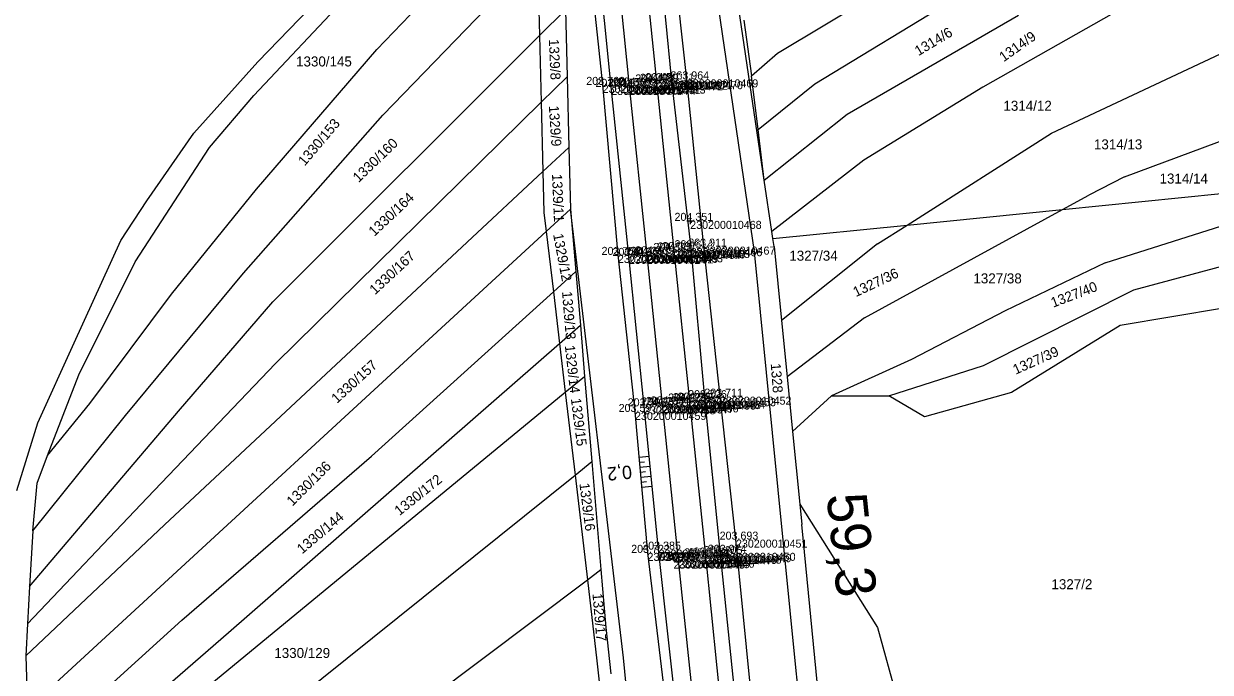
# Model space of a CAD drawing. Extents: x -563148 to -561712, y -1182311 to -1179502.
# Drawn here: x -562607.2 to -562429.3, y -1181480.3 to -1181383.1 of the extents above; entities that cross this region are included whole.
import ezdxf

# ---------------------------------------------------------------- set-up
doc = ezdxf.new("R2010")
doc.units = 0
for name, color, linetype in [('Vrstva 1', 7, 'Continuous'), ('Vrstva 4', 7, 'Continuous'), ('Vrstva 48', 7, 'Continuous'), ('Vrstva 49', 7, 'Continuous'), ('Vrstva 53', 7, 'Continuous'), ('Vrstva 55', 7, 'Continuous'), ('Vrstva 57', 7, 'Continuous'), ('Vrstva 60', 7, 'Continuous'), ('Vrstva 61', 7, 'Continuous'), ('Vrstva 7', 7, 'Continuous')]:
    doc.layers.add(name, color=color, linetype=linetype)

msp = doc.modelspace()

# ---------------------------------------------------------------- linework, layer by layer
at = {"layer": 'Vrstva 1'}
for points in [[(-562538.22, -1181140.47), (-562535.7, -1181165), (-562533.31, -1181188.28), (-562530.86, -1181211.96), (-562528.58, -1181233.98), (-562526.26, -1181256.44), (-562523.94, -1181279), (-562521.9, -1181298.94), (-562519.98, -1181317.53), (-562517.8, -1181338.73), (-562515.33, -1181362.72), (-562512.33, -1181391.8), (-562509.71, -1181417.08), (-562507.39, -1181439.64), (-562504.99, -1181462.85), (-562502.4, -1181488), (-562497.18, -1181538.47), (-562494.78, -1181561.72), (-562492, -1181588.79)], [(-562542.31, -1181141.05), (-562539.78, -1181165.62), (-562537.38, -1181188.86), (-562535, -1181212.18), (-562532.67, -1181234.54), (-562530.35, -1181257.17), (-562528.02, -1181279.67), (-562526.02, -1181298.95), (-562524.04, -1181318.17), (-562521.85, -1181339.36), (-562519.38, -1181363.29), (-562516.39, -1181392.45), (-562513.77, -1181417.73), (-562511.45, -1181440.22), (-562509.05, -1181463.48), (-562506.44, -1181488.7), (-562501.23, -1181539.12), (-562498.83, -1181562.33), (-562496.03, -1181589.56)]]:
    msp.add_lwpolyline(points, dxfattribs=at)
at = {"layer": 'Vrstva 4'}
for points in [[(-562530.95, -1181181.8), (-562531.11, -1181188.17), (-562528.51, -1181211.79), (-562526.22, -1181233.69), (-562523.84, -1181256.06), (-562521.66, -1181278.67), (-562519.62, -1181298.82), (-562517.74, -1181317.29), (-562515.5, -1181338.48), (-562512.91, -1181362.61), (-562510.06, -1181391.72), (-562507.16, -1181416.74), (-562505.12, -1181439.21), (-562502.78, -1181462.58), (-562500.17, -1181487.79), (-562494.92, -1181538.43), (-562492.69, -1181561.57), (-562489.58, -1181589.45)], [(-562492.85, -1181639.28), (-562495.8, -1181615.87), (-562498.53, -1181589.76), (-562501.43, -1181562.22), (-562503.74, -1181539.41), (-562508.99, -1181488.94), (-562512, -1181461.9), (-562514.18, -1181440.43), (-562516.46, -1181417.89), (-562519.11, -1181392.57), (-562522.07, -1181363.22), (-562524.36, -1181339.65), (-562526.91, -1181316.04), (-562528.67, -1181299.17), (-562530.86, -1181280.31), (-562533.06, -1181257.38), (-562535.11, -1181235.07), (-562537.81, -1181212.62), (-562539.6, -1181193.44), (-562540.41, -1181189.21)]]:
    msp.add_lwpolyline(points, dxfattribs=at)
at = {"layer": 'Vrstva 48'}
for p, q in [((-562514.93, -1181448.04), (-562513.42, -1181447.9)), ((-562514.87, -1181448.79), (-562514.11, -1181448.72)), ((-562514.8, -1181449.53), (-562513.27, -1181449.4)), ((-562514.73, -1181450.28), (-562513.96, -1181450.21)), ((-562514.67, -1181451.03), (-562513.12, -1181450.89)), ((-562514.6, -1181451.77), (-562513.82, -1181451.7)), ((-562514.54, -1181452.52), (-562512.97, -1181452.38))]:
    msp.add_line(p, q, dxfattribs=at)
at = {"layer": 'Vrstva 49'}
for points in [[(-562512.91, -1181362.61), (-562510.06, -1181391.72), (-562507.16, -1181416.74), (-562505.12, -1181439.21), (-562502.79, -1181438.98)], [(-562502.79, -1181438.98), (-562505.2, -1181416.5), (-562507.77, -1181391.44), (-562510.96, -1181362.42)], [(-562494.74, -1181639.25), (-562492.85, -1181639.28), (-562495.8, -1181615.87), (-562498.53, -1181589.76), (-562501.43, -1181562.22), (-562503.74, -1181539.41), (-562508.99, -1181488.94), (-562512, -1181461.9), (-562514.18, -1181440.43), (-562516.46, -1181417.89), (-562519.11, -1181392.57), (-562522.07, -1181363.22), (-562523.47, -1181363.71)], [(-562523.47, -1181363.71), (-562520.39, -1181392.27), (-562518.1, -1181417.74), (-562515.54, -1181441.27), (-562513.66, -1181462.38), (-562510.65, -1181487.32), (-562505.3, -1181539.56), (-562502.96, -1181562.74), (-562500.08, -1181589.68), (-562497.19, -1181615.94), (-562494.74, -1181639.25)], [(-562505.12, -1181439.21), (-562502.78, -1181462.58), (-562500.17, -1181487.79), (-562494.92, -1181538.43), (-562492.69, -1181561.57), (-562489.58, -1181589.45)], [(-562487.28, -1181589.39), (-562490.19, -1181561.46), (-562492.66, -1181538.42), (-562497.73, -1181487.61), (-562500.4, -1181460.4), (-562502.79, -1181438.98)]]:
    msp.add_lwpolyline(points, dxfattribs=at)
at = {"layer": 'Vrstva 53'}
for p, q in [((-562508.1, -1181346.18), (-562497.67, -1181417.28)), ((-562525.96, -1181381), (-562525.71, -1181391.05)), ((-562525.71, -1181391.05), (-562525.44, -1181401.63)), ((-562525.44, -1181401.63), (-562525.2, -1181410.9)), ((-562517.26, -1181478.11), (-562525.2, -1181410.9)), ((-562497.67, -1181417.28), (-562491.4, -1181480.04)), ((-562490.83, -1181455.09), (-562490.53, -1181458.12)), ((-562490.83, -1181455.09), (-562479.17, -1181473.55)), ((-562485.92, -1181504.93), (-562490.53, -1181458.12)), ((-562479.17, -1181473.55), (-562475.52, -1181486.71)), ((-562512.39, -1181525.85), (-562517.26, -1181478.11)), ((-562491.4, -1181480.04), (-562486.34, -1181530.82))]:
    msp.add_line(p, q, dxfattribs=at)
at = {"layer": 'Vrstva 55'}
for p, q in [((-562496.16, -1181406.56), (-562506.26, -1181338.06)), ((-562572.09, -1181388.82), (-562543.24, -1181358.92)), ((-562572.69, -1181393.84), (-562552.68, -1181372.65)), ((-562554.24, -1181386.95), (-562541.12, -1181373.3)), ((-562530.13, -1181373.52), (-562529.84, -1181384.88)), ((-562494.15, -1181387.54), (-562469.92, -1181372.94)), ((-562553.33, -1181396.83), (-562533.85, -1181376.68)), ((-562488.56, -1181392.09), (-562463.14, -1181376.59)), ((-562436.7, -1181377.49), (-562463.4, -1181392.62)), ((-562529.84, -1181384.88), (-562525.96, -1181381)), ((-562483.72, -1181396.66), (-562458.06, -1181381.81)), ((-562499.23, -1181382.59), (-562498.05, -1181390.93)), ((-562569.83, -1181424.78), (-562529.84, -1181384.88)), ((-562529.84, -1181384.88), (-562529.59, -1181394.87)), ((-562453.11, -1181399.51), (-562423.6, -1181385.66)), ((-562572.3, -1181407.88), (-562554.24, -1181386.95)), ((-562498.05, -1181390.93), (-562494.15, -1181387.54)), ((-562581.7, -1181399.48), (-562572.09, -1181388.82)), ((-562529.59, -1181394.87), (-562525.71, -1181391.05)), ((-562497.08, -1181398.97), (-562498.05, -1181390.93)), ((-562497.08, -1181398.97), (-562488.56, -1181392.09)), ((-562463.4, -1181392.62), (-562481.25, -1181403.57)), ((-562579.32, -1181401.64), (-562572.69, -1181393.84)), ((-562569.44, -1181434.01), (-562529.59, -1181394.87)), ((-562529.59, -1181394.87), (-562529.33, -1181405.26)), ((-562496.16, -1181406.56), (-562483.72, -1181396.66)), ((-562574.25, -1181420.49), (-562553.33, -1181396.83)), ((-562588.72, -1181409.62), (-562581.7, -1181399.48)), ((-562496.16, -1181406.56), (-562497.08, -1181398.97)), ((-562474.75, -1181413.27), (-562453.11, -1181399.51)), ((-562442.17, -1181406.03), (-562426.15, -1181400.08)), ((-562590.49, -1181418.8), (-562579.32, -1181401.64)), ((-562529.33, -1181405.26), (-562525.44, -1181401.63)), ((-562481.25, -1181403.57), (-562495.02, -1181414.26)), ((-562586.08, -1181458.19), (-562529.33, -1181405.26)), ((-562529.33, -1181405.26), (-562529.18, -1181411.37)), ((-562495.02, -1181414.26), (-562496.16, -1181406.56)), ((-562442.17, -1181406.03), (-562447.51, -1181408.78)), ((-562585.04, -1181423.61), (-562572.3, -1181407.88)), ((-562451.45, -1181410.94), (-562427.65, -1181408.55)), ((-562451.45, -1181410.94), (-562447.51, -1181408.78)), ((-562592.61, -1181415.6), (-562588.72, -1181409.62)), ((-562528.84, -1181414.25), (-562525.2, -1181410.9)), ((-562525.2, -1181410.9), (-562524.41, -1181420.25)), ((-562481.12, -1181427.16), (-562451.45, -1181410.94)), ((-562474.75, -1181413.27), (-562451.45, -1181410.94)), ((-562529.18, -1181411.37), (-562528.84, -1181414.25)), ((-562606.6, -1181485.75), (-562528.84, -1181414.25)), ((-562528.84, -1181414.25), (-562527.77, -1181423.29)), ((-562494.87, -1181415.29), (-562495.02, -1181414.26)), ((-562494.87, -1181415.29), (-562474.75, -1181413.27)), ((-562479.16, -1181416.08), (-562474.75, -1181413.27)), ((-562445.04, -1181418.94), (-562426.62, -1181413.09)), ((-562599.63, -1181430.94), (-562592.61, -1181415.6)), ((-562494.69, -1181416.49), (-562494.87, -1181415.29)), ((-562479.16, -1181416.08), (-562493.58, -1181427.59)), ((-562494.69, -1181416.49), (-562493.58, -1181427.59)), ((-562598.94, -1181435.7), (-562590.49, -1181418.8)), ((-562445.04, -1181418.94), (-562460.02, -1181426.11)), ((-562440.74, -1181422.98), (-562425.33, -1181418.81)), ((-562591.92, -1181441.81), (-562574.25, -1181420.49)), ((-562527.77, -1181423.29), (-562524.41, -1181420.25)), ((-562524.41, -1181420.25), (-562523.73, -1181428.29)), ((-562555.02, -1181447.92), (-562527.77, -1181423.29)), ((-562527.77, -1181423.29), (-562526.86, -1181431.02)), ((-562463.27, -1181434.32), (-562440.74, -1181422.98)), ((-562597.25, -1181439.99), (-562585.04, -1181423.61)), ((-562584, -1181441.16), (-562569.83, -1181424.78)), ((-562460.02, -1181426.11), (-562474.09, -1181433.41)), ((-562427.32, -1181425.71), (-562442.82, -1181428.33)), ((-562526.86, -1181431.02), (-562523.73, -1181428.29)), ((-562523.73, -1181428.29), (-562523.09, -1181435.94)), ((-562493.58, -1181427.59), (-562492.74, -1181436)), ((-562481.12, -1181427.16), (-562492.74, -1181436)), ((-562442.82, -1181428.33), (-562459.11, -1181438.36)), ((-562605.09, -1181442.89), (-562599.63, -1181430.94)), ((-562576.46, -1181474.31), (-562526.86, -1181431.02)), ((-562526.86, -1181431.02), (-562526, -1181438.33)), ((-562588.67, -1181454.16), (-562569.44, -1181434.01)), ((-562474.09, -1181433.41), (-562486.07, -1181438.88)), ((-562603.62, -1181447.79), (-562598.94, -1181435.7)), ((-562526, -1181438.33), (-562523.09, -1181435.94)), ((-562523.09, -1181435.94), (-562522.02, -1181448.7)), ((-562477.47, -1181438.88), (-562463.27, -1181434.32)), ((-562492.74, -1181436), (-562491.92, -1181444.19)), ((-562605.95, -1181504.08), (-562526, -1181438.33)), ((-562526, -1181438.33), (-562524.53, -1181450.72)), ((-562491.92, -1181444.19), (-562486.07, -1181438.88)), ((-562486.07, -1181438.88), (-562477.47, -1181438.88)), ((-562472.13, -1181442.01), (-562477.47, -1181438.88)), ((-562459.11, -1181438.36), (-562472.13, -1181442.01)), ((-562606.34, -1181467.42), (-562584, -1181441.16)), ((-562603.62, -1181447.79), (-562597.25, -1181439.99)), ((-562608.21, -1181453.03), (-562605.09, -1181442.89)), ((-562605.82, -1181459.1), (-562591.92, -1181441.81)), ((-562491.92, -1181444.19), (-562490.83, -1181455.09)), ((-562605.18, -1181451.95), (-562603.62, -1181447.79)), ((-562583.47, -1181472.49), (-562555.02, -1181447.92)), ((-562524.53, -1181450.72), (-562522.02, -1181448.7)), ((-562522.02, -1181448.7), (-562520.65, -1181464.9)), ((-562605.82, -1181459.1), (-562605.18, -1181451.95)), ((-562605.56, -1181515.78), (-562524.53, -1181450.72)), ((-562524.53, -1181450.72), (-562522.68, -1181466.42)), ((-562606.6, -1181473.01), (-562588.67, -1181454.16)), ((-562606.86, -1181477.82), (-562586.08, -1181458.19)), ((-562605.82, -1181459.1), (-562606.34, -1181467.42)), ((-562522.68, -1181466.42), (-562520.65, -1181464.9)), ((-562520.65, -1181464.9), (-562519.92, -1181473.56)), ((-562606.34, -1181467.42), (-562606.6, -1181473.01)), ((-562605.04, -1181528.26), (-562522.68, -1181466.42)), ((-562522.68, -1181466.42), (-562521.24, -1181478.58)), ((-562606.6, -1181473.01), (-562606.86, -1181477.82)), ((-562606.21, -1181493.03), (-562583.47, -1181472.49)), ((-562606.21, -1181500.05), (-562576.46, -1181474.31)), ((-562519.92, -1181473.56), (-562519.18, -1181480.5)), ((-562606.86, -1181477.82), (-562606.6, -1181485.75)), ((-562521.24, -1181478.58), (-562520.92, -1181481.71))]:
    msp.add_line(p, q, dxfattribs=at)
at = {"layer": 'Vrstva 60'}
for p, q in [((-562507.77, -1181391.44), (-562507.77, -1181391.44)), ((-562520.39, -1181392.27), (-562520.39, -1181392.27)), ((-562519.11, -1181392.57), (-562519.11, -1181392.57)), ((-562517.1, -1181392.53), (-562517.1, -1181392.53)), ((-562516.39, -1181392.45), (-562516.39, -1181392.45)), ((-562515.67, -1181392.37), (-562515.67, -1181392.37)), ((-562513.05, -1181391.9), (-562513.05, -1181391.9)), ((-562512.33, -1181391.8), (-562512.33, -1181391.8)), ((-562511.62, -1181391.71), (-562511.62, -1181391.71)), ((-562510.06, -1181391.72), (-562510.06, -1181391.72)), ((-562507.26, -1181412.64), (-562507.26, -1181412.64)), ((-562518.1, -1181417.74), (-562518.1, -1181417.74)), ((-562516.46, -1181417.89), (-562516.46, -1181417.89)), ((-562514.48, -1181417.82), (-562514.48, -1181417.82)), ((-562513.77, -1181417.73), (-562513.77, -1181417.73)), ((-562513.06, -1181417.65), (-562513.06, -1181417.65)), ((-562510.42, -1181417.15), (-562510.42, -1181417.15)), ((-562509.71, -1181417.08), (-562509.71, -1181417.08)), ((-562509, -1181417.01), (-562509, -1181417.01)), ((-562507.16, -1181416.74), (-562507.16, -1181416.74)), ((-562505.2, -1181416.5), (-562505.2, -1181416.5)), ((-562505.12, -1181439.21), (-562505.12, -1181439.21)), ((-562502.79, -1181438.98), (-562502.79, -1181438.98)), ((-562515.54, -1181441.27), (-562515.54, -1181441.27)), ((-562514.18, -1181440.43), (-562514.18, -1181440.43)), ((-562512.16, -1181440.3), (-562512.16, -1181440.3)), ((-562511.45, -1181440.22), (-562511.45, -1181440.22)), ((-562510.73, -1181440.14), (-562510.73, -1181440.14)), ((-562508.1, -1181439.71), (-562508.1, -1181439.71)), ((-562507.39, -1181439.64), (-562507.39, -1181439.64)), ((-562506.68, -1181439.57), (-562506.68, -1181439.57)), ((-562500.4, -1181460.4), (-562500.4, -1181460.4)), ((-562513.66, -1181462.38), (-562513.66, -1181462.38)), ((-562512, -1181461.9), (-562512, -1181461.9)), ((-562502.78, -1181462.58), (-562502.78, -1181462.58)), ((-562502.17, -1181462.37), (-562502.17, -1181462.37)), ((-562509.77, -1181463.55), (-562509.77, -1181463.55)), ((-562509.05, -1181463.48), (-562509.05, -1181463.48)), ((-562508.34, -1181463.41), (-562508.34, -1181463.41)), ((-562505.7, -1181462.91), (-562505.7, -1181462.91)), ((-562504.99, -1181462.85), (-562504.99, -1181462.85)), ((-562504.28, -1181462.79), (-562504.28, -1181462.79))]:
    msp.add_line(p, q, dxfattribs=at)
at = {"layer": 'Vrstva 7'}
for p, q in [((-562507.76, -1181412.64), (-562506.76, -1181412.64)), ((-562507.26, -1181412.14), (-562507.26, -1181413.14)), ((-562502.16, -1181462.42), (-562502.17, -1181462.32))]:
    msp.add_line(p, q, dxfattribs=at)
for centre, radius in [((-562509.09, -1181463.09), 0.75), ((-562502.17, -1181462.37), 0.5)]:
    msp.add_circle(centre, radius, dxfattribs=at)

# ---------------------------------------------------------------- texts
at = {"layer": 'Vrstva 48'}
msp.add_text('0,2', height=2, rotation=185.0862, dxfattribs=at).set_placement((-562516.09, -1181449.26))
at = {"layer": 'Vrstva 57'}
for s, rotation, p in [('1314/6', 30.9182, (-562473.04, -1181387.98)), ('1314/9', 35.2606, (-562460.27, -1181388.89)), ('1329/8', 272.5637, (-562528.46, -1181385.43)), ('1329/9', 273.8388, (-562528.46, -1181395.41)), ('1330/153', 49.8248, (-562565.05, -1181404.5)), ('1330/160', 43.8577, (-562556.98, -1181406.98)), ('1329/11', 272.4026, (-562527.98, -1181405.63)), ('1330/164', 43.2418, (-562554.63, -1181415.06)), ('1329/12', 280.7389, (-562527.82, -1181414.68)), ('1330/167', 42.9241, (-562554.5, -1181423.79)), ('1327/36', 25.1398, (-562482.42, -1181424.08)), ('1329/13', 274.6987, (-562526.48, -1181423.25)), ('1327/40', 20.8956, (-562452.85, -1181425.66)), ('1329/14', 276.3833, (-562526.06, -1181431.34)), ('1327/39', 24.0176, (-562458.47, -1181435.7)), ('1330/157', 42.2803, (-562560.23, -1181440.08)), ('1328', 274.3647, (-562495.19, -1181434.03)), ('1329/15', 277.384, (-562525.16, -1181439.28)), ('1330/136', 45, (-562566.88, -1181455.46)), ('1330/172', 38.6717, (-562550.85, -1181456.89)), ('1329/16', 277.3057, (-562523.88, -1181452)), ('1330/144', 40.1882, (-562565.44, -1181462.62)), ('1329/17', 274.8963, (-562521.92, -1181468.49))]:
    msp.add_text(s, height=1.5, rotation=rotation, dxfattribs=at).set_placement(p)
for s, p in [('1330/145', (-562566.35, -1181389.51)), ('1314/12', (-562460.3, -1181396.15)), ('1314/13', (-562446.73, -1181401.93)), ('1314/14', (-562436.89, -1181407.05)), ('1327/34', (-562492.4, -1181418.61)), ('1327/38', (-562464.8, -1181422.01)), ('1327/2', (-562453.1, -1181467.83)), ('1330/129', (-562569.61, -1181478.13))]:
    msp.add_text(s, height=1.5, dxfattribs=at).set_placement(p)
at = {"layer": 'Vrstva 60'}
for s, p in [('230200010469', (-562507.77, -1181392.64)), ('230200010476', (-562520.39, -1181393.47)), ('230200010475', (-562519.11, -1181393.78)), ('230200010474', (-562517.1, -1181393.73)), ('230200011451', (-562516.39, -1181393.65)), ('230200010473', (-562515.67, -1181393.57)), ('230200010472', (-562513.05, -1181393.1)), ('230200011452', (-562512.33, -1181393.01)), ('230200010471', (-562511.62, -1181392.91)), ('230200010470', (-562510.06, -1181392.92)), ('230200010468', (-562507.26, -1181413.84)), ('230200010460', (-562518.1, -1181418.94)), ('230200010461', (-562516.46, -1181419.09)), ('230200010462', (-562514.48, -1181419.02)), ('230200011449', (-562513.77, -1181418.93)), ('230200010463', (-562513.06, -1181418.85)), ('230200010464', (-562510.42, -1181418.35)), ('230200011450', (-562509.71, -1181418.28)), ('230200010465', (-562509, -1181418.21)), ('230200010466', (-562507.16, -1181417.94)), ('230200010467', (-562505.2, -1181417.7)), ('230200010453', (-562505.12, -1181440.41)), ('230200010452', (-562502.79, -1181440.18)), ('230200010459', (-562515.54, -1181442.47)), ('230200010458', (-562514.18, -1181441.63)), ('230200010457', (-562512.16, -1181441.5)), ('230200011447', (-562511.45, -1181441.42)), ('230200010456', (-562510.73, -1181441.34)), ('230200010455', (-562508.1, -1181440.91)), ('230200011448', (-562507.39, -1181440.84)), ('230200010454', (-562506.68, -1181440.77)), ('230200010451', (-562500.4, -1181461.6)), ('230200010443', (-562513.66, -1181463.58)), ('230200010444', (-562512, -1181463.1)), ('230200010449', (-562502.78, -1181463.78)), ('230200010450', (-562502.17, -1181463.57)), ('230200010445', (-562509.77, -1181464.75)), ('230200011445', (-562509.05, -1181464.68)), ('230200010446', (-562508.34, -1181464.61)), ('230200010447', (-562505.7, -1181464.1)), ('230200011446', (-562504.99, -1181464.05)), ('230200010448', (-562504.28, -1181463.99))]:
    msp.add_text(s, height=1.2, dxfattribs=at).set_placement(p)
at = {"layer": 'Vrstva 61'}
for s, p in [('203.760', (-562522.84, -1181392.27)), ('203.811', (-562521.46, -1181392.57)), ('204.510', (-562519.55, -1181392.53)), ('204.509', (-562518.84, -1181392.45)), ('204.509', (-562518.13, -1181392.37)), ('204.489', (-562515.5, -1181391.9)), ('204.489', (-562514.79, -1181391.8)), ('204.501', (-562513.98, -1181391.71)), ('204.011', (-562512.42, -1181391.72)), ('203.964', (-562510.22, -1181391.44)), ('204.351', (-562509.61, -1181412.64)), ('204.341', (-562512.78, -1181417.15)), ('204.337', (-562512.16, -1181417.08)), ('204.337', (-562511.45, -1181417.01)), ('203.814', (-562509.61, -1181416.74)), ('203.911', (-562507.55, -1181416.5)), ('203.756', (-562520.55, -1181417.74)), ('203.619', (-562518.91, -1181417.89)), ('204.369', (-562516.93, -1181417.82)), ('204.363', (-562516.22, -1181417.73)), ('204.363', (-562515.51, -1181417.65)), ('203.506', (-562516.63, -1181440.43)), ('204.237', (-562514.61, -1181440.3)), ('204.234', (-562513.9, -1181440.22)), ('204.234', (-562513.18, -1181440.14)), ('204.225', (-562510.56, -1181439.71)), ('204.225', (-562509.85, -1181439.64)), ('204.232', (-562509.13, -1181439.57)), ('203.726', (-562507.57, -1181439.21)), ('203.711', (-562505.15, -1181438.98)), ('203.597', (-562517.99, -1181441.27)), ('203.385', (-562514.45, -1181461.9)), ('203.693', (-562502.85, -1181460.4)), ('203.722', (-562516.11, -1181462.38)), ('204.095', (-562512.22, -1181463.55)), ('204.087', (-562511.5, -1181463.48)), ('204.087', (-562510.79, -1181463.41)), ('204.097', (-562508.16, -1181462.91)), ('204.097', (-562507.45, -1181462.85)), ('204.097', (-562506.73, -1181462.79)), ('203.605', (-562505.24, -1181462.58)), ('203.974', (-562504.62, -1181462.37))]:
    msp.add_text(s, height=1.2, dxfattribs=at).set_placement(p)
at = {"layer": 'Vrstva 7'}
msp.add_text('59,3', height=6, rotation=275.8764, dxfattribs=at).set_placement((-562486.82, -1181453.71))

doc.saveas('drawing.dxf')
